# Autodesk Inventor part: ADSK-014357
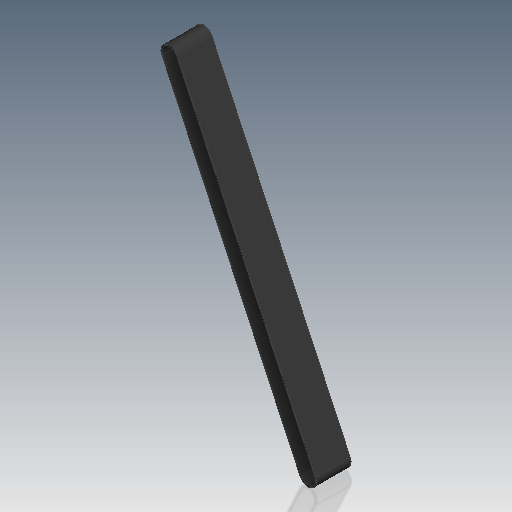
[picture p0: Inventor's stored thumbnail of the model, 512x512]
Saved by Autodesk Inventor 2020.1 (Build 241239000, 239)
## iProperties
Created: 2000-03
Part Number: ADSK-014357
Material: Pearson HRS
Description: CHAIN,MATTOP,FLUSH GRID,9.00W X 1.00 PITCH, LF, 2100 SERIES
Document SubType Name: Modeling
Designer: cmcgourin
Density: 7.83 g/cm^3
Appearance: Rubber-Black
Mass: 67764 g
Surface Area: 22388.6 cm^2
Volume: 8654.4 cm^3
Control State: 0
Master: False
Checked Out: False
Shininess: 0.0
Length Units: 11269
Angle Units: 11279
Time Units: 11290
Mass Units: 11283
Length Display Precision: 3
Angle Display Precision: 2
Compacted: True
Cutlength: 23.25
Material Desc: Material Description goes here
Material_Number: Pearson
Dimensions: 2093,3x230x1039,9 mm
Mass: 67,764 kg
VLT_Material: Pearson HRS
DocNumber: ADSK-014357
Folder: 01 - Themengebiete\Simplification\01 - Packaging machine\
Original: C:\AB_Vault\CAD\01 - Themengebiete\Simplification\01 - Packaging machine\Parts\ADSK-011840.ipt
VDS_Category: 3D Komponenten
VDS_NumSchm: Autodesk
Density: 0.0
Volumn: 0.0
Area: 0.0
PropertySet Name: Model Information
Author: cmcgourin
Revision Number: -
Title: belt
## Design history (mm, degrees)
feature "Fläche5"
node "Flä5"
feature "Fläche6"
node "Flä6"
feature "Fläche7"
node "Flä7"
feature "Fläche8"
node "Flä8"
workplane "Arbeitsebene3"
sketch "Skizze2"
  geometry: L1 (1492.679, -1593.915)-(22.5, 22.5); L2 (1528.984, -1560.895)-(58.805, 55.52); L3 (-13.805, -10.52)-(1456.374, -1626.936); L4 (64.723, 60.903)-(1534.902, -1555.512); L5 (1450.456, -1632.318)-(-19.723, -15.903); C1 r 49.075 at (22.5, 22.5) reference; C2 r 49.075 at (1492.679, -1593.915) reference; A1 r 49.075 centre (1492.679, -1593.915) between (1456.374, -1626.936) and (1528.984, -1560.895); A2 r 49.075 centre (22.5, 22.5) between (58.805, 55.52) and (-13.805, -10.52); A3 r 57.075 centre (1492.679, -1593.915) between (1450.456, -1632.318) and (1534.902, -1555.512); A4 r 57.075 centre (22.5, 22.5) between (64.723, 60.903) and (-19.723, -15.903); 2 further points
  constraints: 12 end point, 8 point on circle, 4 centre point, 4 tangent, 2 parallel, 1 concentric, 1 midpoint, 3 other
  dimensions: "d5" = 8 distance between parallel lines of L2 L4
extrude "Extrusion2" new body sketch "Skizze2" stored distance "d6" = 230; taper "d7" = 0 deg
node "Volumenkörper2"
node "Corps solides"
node "Corps surfaciques"
